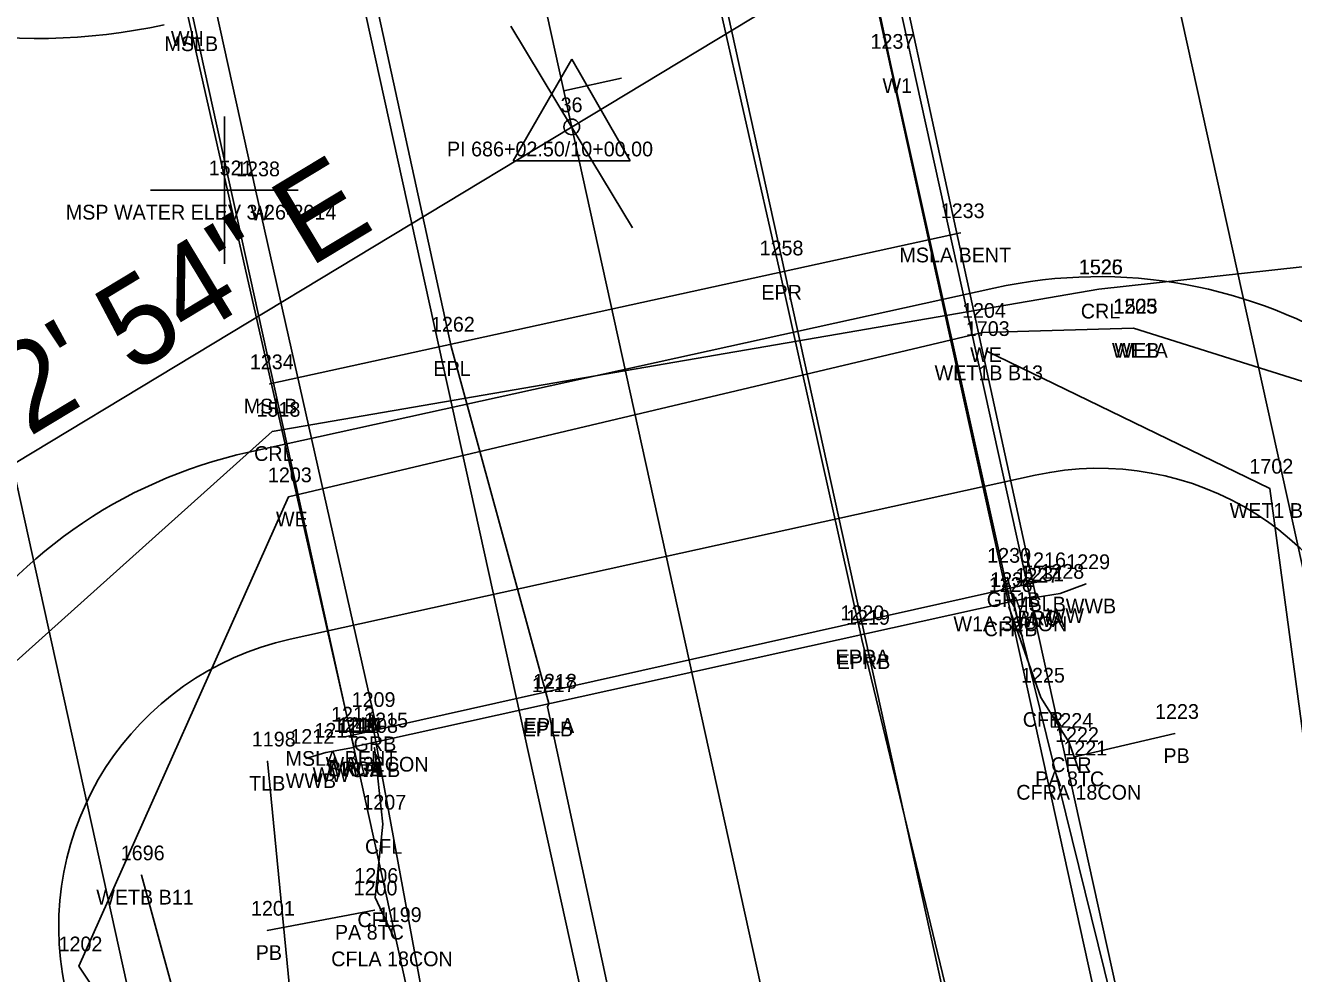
# Model space of a CAD drawing. Extents: x 2520975 to 2526538, y 881018 to 888064.
# Drawn here: x 2523752.6 to 2523838.7, y 885062.2 to 885126.5 of the extents above; entities that cross this region are included whole.
import ezdxf

# ---------------------------------------------------------------- set-up
doc = ezdxf.new("R2010")
doc.units = 0
for name, color, linetype in [('RD_EV_JurisArea', 7, 'Continuous'), ('RD_EX_BldgApp', 7, 'Continuous'), ('RD_EX_BldgApp_txCode', 7, 'Continuous'), ('RD_EX_Bridge', 7, 'Continuous'), ('RD_EX_Bridge_txCode', 7, 'Continuous'), ('RD_EX_Conc', 7, 'Continuous'), ('RD_EX_Conc_txCode', 7, 'Continuous'), ('RD_EX_DR_Pipe', 7, 'Continuous'), ('RD_EX_DR_Pipe_txCode', 7, 'Continuous'), ('RD_EX_GuardRail', 7, 'Continuous'), ('RD_EX_GuardRail_txCode', 7, 'Continuous'), ('RD_EX_H2O', 7, 'Continuous'), ('RD_EX_H2O_txCode', 7, 'Continuous'), ('RD_EX_H2O_WetLd_txCode', 7, 'Continuous'), ('RD_EX_Misc', 7, 'Continuous'), ('RD_EX_Misc_txCode', 7, 'Continuous'), ('RD_EX_Road', 7, 'Continuous'), ('RD_EX_Road_txCode', 7, 'Continuous'), ('RD_EX_VEG', 7, 'Continuous'), ('RD_EX_VEG_txCode', 7, 'Continuous'), ('RD_HC_Cl', 7, 'Continuous'), ('RD_HC_Data', 7, 'Continuous'), ('RD_HC_Data_Tic', 7, 'Continuous'), ('RD_HC_txCode', 7, 'Continuous'), ('RD_PD_BCA', 7, 'Continuous'), ('RD_PD_Bridge', 7, 'Continuous'), ('RD_PD_CstnLmt', 7, 'Continuous'), ('RD_PD_DR_ErosCtrl', 7, 'Continuous'), ('RD_PD_Final_TrvlWay', 7, 'Continuous'), ('RD_SMD_Locator', 7, 'Continuous')]:
    doc.layers.add(name, color=color, linetype=linetype)

msp = doc.modelspace()

# ---------------------------------------------------------------- linework, layer by layer
at = {"layer": 'RD_EV_JurisArea'}
for points in [[(2523944.864, 884550.08), (2523910.413, 884709.577), (2523888.007, 884815.03), (2523863.93, 884918.366), (2523848.427, 885010.841), (2523837.066, 885095.132), (2523817.825, 885104.474)], [(2523827.748, 884469.643), (2523867.429, 884517.673), (2523885.95, 884534.838), (2523882.771, 884582.718), (2523847.739, 884736.424), (2523822.93, 884833.786), (2523804.257, 884914.891), (2523780.91, 884992.763), (2523770.735, 885031.476), (2523760.496, 885068.896)]]:
    msp.add_lwpolyline(points, dxfattribs=at)
at = {"layer": 'RD_EX_BldgApp'}
for points in [[(2523819.439, 885087.441), (2523811.319, 885123.961), (2523803.308, 885161.503)], [(2523776.677, 885077.915), (2523768.273, 885115.309), (2523760.204, 885151.895)]]:
    msp.add_lwpolyline(points, dxfattribs=at)
at = {"layer": 'RD_EX_Bridge'}
for points in [[(2523774.906, 885077.596), (2523821.197, 885087.829), (2523805.064, 885161.895), (2523758.145, 885151.437), (2523774.906, 885077.596)], [(2523821.146, 885087.728), (2523822.84, 885087.999), (2523824.599, 885088.655)], [(2523774.897, 885077.54), (2523773.018, 885077.212), (2523771.668, 885076.8)]]:
    msp.add_lwpolyline(points, dxfattribs=at)
at = {"layer": 'RD_EX_Conc'}
for points in [[(2523824.118, 885076.01), (2523823.453, 885077.886), (2523821.532, 885080.953), (2523819.362, 885087.102)], [(2523777.605, 885064.707), (2523776.362, 885067.363), (2523776.876, 885072.337), (2523776.323, 885077.543)]]:
    msp.add_lwpolyline(points, dxfattribs=at)
at = {"layer": 'RD_EX_DR_Pipe'}
for p, q in [((2523823.84, 885076.923), (2523830.626, 885078.493)), ((2523776.322, 885066.515), (2523769.037, 885065.137))]:
    msp.add_line(p, q, dxfattribs=at)
at = {"layer": 'RD_EX_GuardRail'}
for points in [[(2523841.112, 885013.814), (2523827.604, 885055.265), (2523819.275, 885089.086)], [(2523787.377, 885001.584), (2523782.908, 885042.685), (2523776.151, 885079.302)]]:
    msp.add_lwpolyline(points, dxfattribs=at)
at = {"layer": 'RD_EX_H2O'}
for points in [[(2523582.816, 884766.342), (2523598.112, 884856.984), (2523627.586, 884901.753), (2523623.762, 884928.278), (2523586.58, 884955.428), (2523600.942, 884974.118), (2523633.055, 884997.681), (2523679.166, 885037.048), (2523744.717, 885076.895), (2523769.376, 885098.995), (2523825.47, 885108.66), (2523825.47, 885108.66), (2523845.237, 885110.828), (2523890.252, 885154.934)], [(2523827.825, 885105.996), (2523850.303, 885098.921), (2523867.326, 885117.194), (2523890.438, 885097.244), (2523927.793, 885098.781), (2523966.352, 885109.501), (2523978.174, 885083.367)], [(2523792.732, 884941.121), (2523763.674, 885051.555), (2523756.264, 885062.719), (2523770.471, 885094.548), (2523817.567, 885105.706), (2523827.825, 885105.996)]]:
    msp.add_lwpolyline(points, dxfattribs=at)
at = {"layer": 'RD_EX_Misc'}
for p, q in [((2523766.128, 885110.375), (2523766.128, 885120.375)), ((2523761.128, 885115.375), (2523771.128, 885115.375)), ((2523816.084, 885112.468), (2523769.205, 885102.217)), ((2523774.429, 885078.307), (2523821.346, 885088.784))]:
    msp.add_line(p, q, dxfattribs=at)
at = {"layer": 'RD_EX_Road'}
for p, q in [((2523803.791, 885109.941), (2523798.302, 885134.145)), ((2523781.516, 885104.768), (2523776.178, 885129.21)), ((2523809.315, 885085.19), (2523803.791, 885109.941)), ((2523788.138, 885080.544), (2523781.516, 885104.768)), ((2523809.375, 885084.881), (2523809.315, 885085.19)), ((2523817.578, 885050.917), (2523809.375, 885084.881)), ((2523788.047, 885080.306), (2523788.138, 885080.544)), ((2523795.465, 885045.906), (2523788.047, 885080.306))]:
    msp.add_line(p, q, dxfattribs=at)
at = {"layer": 'RD_EX_VEG'}
msp.add_lwpolyline([(2523800.231, 884418.22), (2523892.245, 884498.974), (2523844.575, 884752.813), (2523771.945, 885046.883), (2523769.056, 885076.621)], dxfattribs=at)
at = {"layer": 'RD_HC_Cl'}
for p, q in [((2523662.651, 885798.932), (2524219.244, 883271.288)), ((2523641.165, 885794.201), (2524197.759, 883266.557)), ((2523672.044, 885048.634), (2523837.18, 885148.323))]:
    msp.add_line(p, q, dxfattribs=at)
at = {"layer": 'RD_HC_Data'}
for p, q in [((2523785.73, 885117.368), (2523789.702, 885124.248)), ((2523789.702, 885124.248), (2523793.671, 885117.368)), ((2523785.73, 885117.368), (2523793.671, 885117.368))]:
    msp.add_line(p, q, dxfattribs=at)
msp.add_circle((2523789.701, 885119.661), 0.529, dxfattribs=at)
at = {"layer": 'RD_HC_Data_Tic'}
for p, q in [((2523789.692, 885119.656), (2523785.558, 885126.504)), ((2523789.164, 885122.1), (2523793.07, 885122.96)), ((2523789.692, 885119.656), (2523793.827, 885112.807))]:
    msp.add_line(p, q, dxfattribs=at)
at = {"layer": 'RD_PD_BCA'}
msp.add_arc((2523753.452, 885165.659), 40, 192.06773, 282.41848, dxfattribs=at)
at = {"layer": 'RD_PD_Bridge'}
for points in [[(2523826.629, 885061.235), (2523798.673, 885188.194)], [(2523752.772, 885178.086), (2523780.729, 885051.128)]]:
    msp.add_lwpolyline(points, dxfattribs=at)
at = {"layer": 'RD_PD_CstnLmt'}
msp.add_lwpolyline([(2523770.593, 885084.896), (2523821.135, 885096.025)], dxfattribs=at)
for centre, start, end in [((2523825.436, 885076.493), 13.07237, 102.41848), ((2523774.894, 885065.364), 102.41848, 192.06773)]:
    msp.add_arc(centre, 20, start, end, dxfattribs=at)
at = {"layer": 'RD_PD_DR_ErosCtrl'}
msp.add_lwpolyline([(2523767.797, 885097.592), (2523818.34, 885108.721)], dxfattribs=at)
for centre, start, end in [((2523825.436, 885076.493), 13.07237, 102.41848), ((2523774.894, 885065.364), 102.41848, 192.06773)]:
    msp.add_arc(centre, 33, start, end, dxfattribs=at)
at = {"layer": 'RD_PD_Final_TrvlWay'}
for p, q in [((2523712.872, 885663.865), (2524066.737, 884056.869)), ((2523636.679, 885619.273), (2523984.702, 884038.805)), ((2523720.239, 885490.907), (2524037.438, 884050.417)), ((2523696.801, 885485.745), (2524014, 884045.256))]:
    msp.add_line(p, q, dxfattribs=at)
at = {"layer": 'RD_SMD_Locator'}
for centre in [(2523811.319, 885123.961), (2523789.701, 885119.661), (2523768.273, 885115.309), (2523816.084, 885112.468), (2523803.791, 885109.941), (2523825.47, 885108.66), (2523825.47, 885108.66), (2523817.567, 885105.706), (2523827.825, 885105.996), (2523827.825, 885105.996), (2523781.516, 885104.768), (2523817.825, 885104.474), (2523769.205, 885102.217), (2523769.376, 885098.995), (2523837.066, 885095.132), (2523770.471, 885094.548), (2523819.275, 885089.086), (2523821.346, 885088.784), (2523824.599, 885088.655), (2523819.439, 885087.441), (2523821.146, 885087.728), (2523821.197, 885087.829), (2523822.84, 885087.999), (2523819.362, 885087.102), (2523809.315, 885085.19), (2523809.375, 885084.881), (2523788.138, 885080.544), (2523821.532, 885080.953), (2523788.047, 885080.306), (2523776.151, 885079.302), (2523774.429, 885078.307), (2523776.677, 885077.915), (2523823.453, 885077.886), (2523830.626, 885078.493), (2523773.018, 885077.212), (2523774.897, 885077.54), (2523774.906, 885077.596), (2523774.906, 885077.596), (2523776.323, 885077.543), (2523823.84, 885076.923), (2523769.056, 885076.621), (2523771.668, 885076.8), (2523824.118, 885076.01), (2523776.876, 885072.337), (2523760.496, 885068.896), (2523776.362, 885067.363), (2523776.322, 885066.515), (2523769.037, 885065.137), (2523777.605, 885064.707), (2523756.264, 885062.719)]:
    msp.add_circle(centre, 0.001, dxfattribs=at)

# ---------------------------------------------------------------- texts
at = {"layer": 'RD_EX_BldgApp_txCode'}
for s, p in [('WH', (2523762.504, 885125.16)), ('1237', (2523809.973, 885124.961)), ('W1', (2523810.784, 885121.961)), ('1238', (2523766.926, 885116.309)), ('W', (2523767.903, 885113.309)), ('1232', (2523818.093, 885088.441)), ('W1A 32CON', (2523815.597, 885085.441)), ('1215', (2523775.614, 885078.915)), ('WA 32CON', (2523773, 885075.915))]:
    msp.add_text(s, height=1, dxfattribs=at).set_placement(p)
at = {"layer": 'RD_EX_Bridge_txCode'}
for s, p in [('1229', (2523823.253, 885089.655)), ('1231', (2523820.134, 885088.829)), ('1228', (2523821.494, 885088.999)), ('1227', (2523819.799, 885088.728)), ('WWB', (2523823.221, 885086.655)), ('WWA', (2523819.752, 885085.728)), ('BRC', (2523819.945, 885085.829)), ('WW', (2523821.934, 885085.999)), ('1246', (2523773.536, 885078.596)), ('1210', (2523773.795, 885078.54)), ('1214', (2523773.843, 885078.596)), ('1212', (2523770.605, 885077.8)), ('1211', (2523772.238, 885078.212)), ('WW', (2523772.112, 885075.212)), ('BRCA', (2523773.166, 885075.596)), ('BRCB', (2523773.182, 885075.596)), ('WWA', (2523773.503, 885075.54)), ('WWB', (2523770.29, 885074.8))]:
    msp.add_text(s, height=1, dxfattribs=at).set_placement(p)
at = {"layer": 'RD_EX_Conc_txCode'}
for s, p in [('1226', (2523817.992, 885088.102)), ('CFRB', (2523817.661, 885085.102)), ('1225', (2523820.185, 885081.953)), ('1208', (2523774.937, 885078.543)), ('CFR', (2523820.303, 885078.953)), ('1224', (2523822.107, 885078.886)), ('1221', (2523823.055, 885077.01)), ('CFR', (2523822.225, 885075.886)), ('CFLB', (2523774.646, 885075.543)), ('1207', (2523775.491, 885073.337)), ('CFRA 18CON', (2523819.866, 885074.01)), ('CFL', (2523775.672, 885070.337)), ('1206', (2523774.952, 885068.363)), ('1199', (2523776.542, 885065.707)), ('CFL', (2523775.157, 885065.363)), ('CFLA 18CON', (2523773.377, 885062.707))]:
    msp.add_text(s, height=1, dxfattribs=at).set_placement(p)
at = {"layer": 'RD_EX_DR_Pipe_txCode'}
for s, p in [('1223', (2523829.28, 885079.493)), ('1222', (2523822.493, 885077.923)), ('PB', (2523829.846, 885076.493)), ('PA 8TC', (2523821.147, 885074.923)), ('1200', (2523774.897, 885067.515)), ('1201', (2523767.935, 885066.137)), ('PA 8TC', (2523773.629, 885064.515)), ('PB', (2523768.257, 885063.137))]:
    msp.add_text(s, height=1, dxfattribs=at).set_placement(p)
at = {"layer": 'RD_EX_GuardRail_txCode'}
for s, p in [('1230', (2523817.89, 885090.086)), ('GR1B', (2523817.858, 885087.086)), ('1209', (2523774.765, 885080.302)), ('GRB', (2523774.899, 885077.302))]:
    msp.add_text(s, height=1, dxfattribs=at).set_placement(p)
at = {"layer": 'RD_EX_H2O_txCode'}
for s, p in [('1526', (2523824.1, 885109.66)), ('1525', (2523824.124, 885109.66)), ('1205', (2523826.44, 885106.996)), ('1523', (2523826.479, 885106.996)), ('1204', (2523816.181, 885106.706)), ('CRL', (2523824.242, 885106.66)), ('CRL', (2523824.242, 885106.66)), ('WE', (2523816.729, 885103.706)), ('WE1A', (2523826.353, 885103.996)), ('WEB', (2523826.534, 885103.996)), ('1518', (2523768.313, 885099.995)), ('CRL', (2523768.148, 885096.995)), ('1203', (2523769.085, 885095.548)), ('WE', (2523769.632, 885092.548)), ('1202', (2523754.878, 885063.719))]:
    msp.add_text(s, height=1, dxfattribs=at).set_placement(p)
at = {"layer": 'RD_EX_H2O_WetLd_txCode'}
for s, p in [('1703', (2523816.439, 885105.474)), ('WET1B B13', (2523814.321, 885102.474)), ('1702', (2523835.68, 885096.132)), ('WET1 B14', (2523834.341, 885093.132)), ('1696', (2523759.102, 885069.896)), ('WETB B11', (2523757.44, 885066.896))]:
    msp.add_text(s, height=1, dxfattribs=at).set_placement(p)
at = {"layer": 'RD_EX_Misc_txCode'}
for s, p in [('MSLB', (2523762.066, 885124.803)), ('1521', (2523765.065, 885116.375)), ('MSP WATER ELEV 3-26-2014', (2523755.372, 885113.375)), ('1233', (2523814.737, 885113.468)), ('MSLA BENT', (2523811.934, 885110.468)), ('1234', (2523767.858, 885103.217)), ('MSLB', (2523767.441, 885100.217)), ('1216', (2523820.259, 885089.784)), ('MSLB', (2523819.582, 885086.784)), ('1213', (2523773.366, 885079.307)), ('MSLA BENT', (2523770.279, 885076.307))]:
    msp.add_text(s, height=1, dxfattribs=at).set_placement(p)
at = {"layer": 'RD_EX_Road_txCode'}
for s, p in [('1258', (2523802.445, 885110.941)), ('EPR', (2523802.563, 885107.941)), ('1262', (2523780.146, 885105.768)), ('EPL', (2523780.311, 885102.768)), ('1220', (2523807.93, 885086.19)), ('1219', (2523808.312, 885085.881)), ('EPRA', (2523807.599, 885083.19)), ('EPRB', (2523807.675, 885082.881)), ('1217', (2523786.984, 885081.306)), ('1218', (2523787.075, 885081.544)), ('EPLA', (2523786.445, 885078.544)), ('EPLB', (2523786.37, 885078.306))]:
    msp.add_text(s, height=1, dxfattribs=at).set_placement(p)
at = {"layer": 'RD_EX_VEG_txCode'}
for s, p in [('1198', (2523767.993, 885077.621)), ('TLB', (2523767.812, 885074.621))]:
    msp.add_text(s, height=1, dxfattribs=at).set_placement(p)
at = {"layer": 'RD_HC_Data'}
msp.add_text('N 58%%d 52\' 54" E', height=6, rotation=31.1184, dxfattribs=at).set_placement((2523729.873, 885084.712))
at = {"layer": 'RD_HC_txCode'}
for s, p in [('36', (2523788.945, 885120.661)), ('PI 686+02.50/10+00.00', (2523781.236, 885117.661))]:
    msp.add_text(s, height=1, dxfattribs=at).set_placement(p)

doc.saveas('drawing.dxf')
